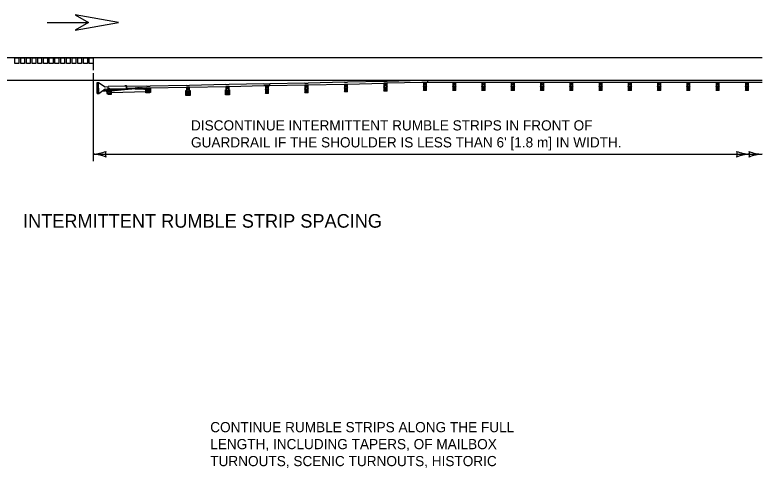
# Model space of a CAD drawing. Extents: x 49991.4 to 50021, y 49987.6 to 50011.4.
# Drawn here: x 50003.185 to 50007.589, y 49993.419 to 49996.09 of the extents above; entities that cross this region are included whole.
import ezdxf

# ---------------------------------------------------------------- set-up
doc = ezdxf.new("R2010")
doc.units = 0
for name, color, linetype in [('Level 1', 7, 'Continuous'), ('Level 2', 7, 'Continuous'), ('Level 3', 7, 'Continuous')]:
    doc.layers.add(name, color=color, linetype=linetype)

msp = doc.modelspace()

# ---------------------------------------------------------------- linework, layer by layer
at = {"layer": 'Level 1'}
for p, q in [((50003.3742, 49996.0445), (50003.6181, 49996.0445)), ((50003.3742, 49996.0443), (50003.6181, 49996.0443)), ((50007.5892, 49995.8373), (50001.3657, 49995.8373)), ((50003.628, 49995.7023), (50001.3657, 49995.7023)), ((50005.7236, 49995.7023), (50003.628, 49995.7023)), ((50003.6688, 49995.6911), (50003.6781, 49995.6913)), ((50003.6701, 49995.6259), (50003.6688, 49995.6911)), ((50003.6772, 49995.6261), (50003.6759, 49995.6913)), ((50003.6794, 49995.6261), (50003.6781, 49995.6913)), ((50003.6781, 49995.6913), (50003.7159, 49995.665)), ((50005.1274, 49995.693), (50004.9132, 49995.6884)), ((50005.1274, 49995.693), (50005.146, 49995.693)), ((50005.3603, 49995.6977), (50005.146, 49995.693)), ((50005.3603, 49995.6977), (50005.3789, 49995.6977)), ((50005.5841, 49995.7023), (50005.3789, 49995.6977)), ((50005.5841, 49995.6919), (50005.3789, 49995.6873)), ((50007.5892, 49995.7023), (50005.5841, 49995.7023)), ((50007.5892, 49995.6919), (50005.5841, 49995.6919)), ((50005.5932, 49995.6919), (50005.6118, 49995.6686)), ((50005.5932, 49995.6686), (50005.6118, 49995.6919)), ((50005.5932, 49995.6919), (50005.5932, 49995.6453)), ((50005.6118, 49995.6453), (50005.6118, 49995.6919)), ((50005.6196, 49995.6919), (50005.6196, 49995.7023)), ((50007.5892, 49995.7023), (50005.7236, 49995.7023)), ((50005.7657, 49995.6919), (50005.7843, 49995.6686)), ((50005.7657, 49995.6686), (50005.7843, 49995.6919)), ((50005.7657, 49995.6919), (50005.7657, 49995.6453)), ((50005.7843, 49995.6453), (50005.7843, 49995.6919)), ((50005.9382, 49995.6919), (50005.9568, 49995.6686)), ((50005.9382, 49995.6686), (50005.9568, 49995.6919)), ((50005.9382, 49995.6919), (50005.9382, 49995.6453)), ((50005.9568, 49995.6453), (50005.9568, 49995.6919)), ((50006.1107, 49995.6919), (50006.1293, 49995.6686)), ((50006.1107, 49995.6686), (50006.1293, 49995.6919)), ((50006.1107, 49995.6919), (50006.1107, 49995.6453)), ((50006.1293, 49995.6453), (50006.1293, 49995.6919)), ((50006.2832, 49995.6919), (50006.3018, 49995.6686)), ((50006.2832, 49995.6686), (50006.3018, 49995.6919)), ((50006.2832, 49995.6919), (50006.2832, 49995.6453)), ((50006.3018, 49995.6453), (50006.3018, 49995.6919)), ((50006.4557, 49995.6919), (50006.4743, 49995.6686)), ((50006.4557, 49995.6686), (50006.4743, 49995.6919)), ((50006.4557, 49995.6919), (50006.4557, 49995.6453)), ((50006.4743, 49995.6453), (50006.4743, 49995.6919)), ((50006.6282, 49995.6919), (50006.6468, 49995.6686)), ((50006.6282, 49995.6686), (50006.6468, 49995.6919)), ((50006.6282, 49995.6919), (50006.6282, 49995.6453)), ((50006.6468, 49995.6453), (50006.6468, 49995.6919)), ((50006.8007, 49995.6919), (50006.8193, 49995.6686)), ((50006.8007, 49995.6686), (50006.8193, 49995.6919)), ((50006.8007, 49995.6919), (50006.8007, 49995.6453)), ((50006.8193, 49995.6453), (50006.8193, 49995.6919)), ((50006.9732, 49995.6919), (50006.9918, 49995.6686)), ((50006.9732, 49995.6686), (50006.9918, 49995.6919)), ((50006.9732, 49995.6919), (50006.9732, 49995.6453)), ((50006.9918, 49995.6453), (50006.9918, 49995.6919)), ((50007.1457, 49995.6919), (50007.1643, 49995.6686)), ((50007.1457, 49995.6686), (50007.1643, 49995.6919)), ((50007.1457, 49995.6919), (50007.1457, 49995.6453)), ((50007.1643, 49995.6453), (50007.1643, 49995.6919)), ((50007.3182, 49995.6919), (50007.3368, 49995.6686)), ((50007.3182, 49995.6686), (50007.3368, 49995.6919)), ((50007.3182, 49995.6919), (50007.3182, 49995.6453)), ((50007.3368, 49995.6453), (50007.3368, 49995.6919)), ((50007.4907, 49995.6919), (50007.5093, 49995.6686)), ((50007.4907, 49995.6686), (50007.5093, 49995.6919)), ((50007.4907, 49995.6919), (50007.4907, 49995.6453)), ((50007.5093, 49995.6453), (50007.5093, 49995.6919)), ((50003.6794, 49995.6261), (50003.7161, 49995.654)), ((50003.7139, 49995.6524), (50003.7142, 49995.64)), ((50003.7159, 49995.665), (50003.7345, 49995.6673)), ((50003.7161, 49995.654), (50003.7348, 49995.6524)), ((50003.7271, 49995.6452), (50003.726, 49995.6452)), ((50003.726, 49995.6363), (50003.726, 49995.6452)), ((50003.7271, 49995.6531), (50003.7271, 49995.6261)), ((50003.7301, 49995.6524), (50003.7301, 49995.6261)), ((50003.7301, 49995.6291), (50003.7487, 49995.6524)), ((50003.7301, 49995.6524), (50003.7487, 49995.6291)), ((50003.7301, 49995.6524), (50003.7547, 49995.6524)), ((50003.8438, 49995.6695), (50003.7345, 49995.6673)), ((50003.7348, 49995.6524), (50003.7345, 49995.6673)), ((50003.8441, 49995.6546), (50003.7348, 49995.6524)), ((50003.7359, 49995.6577), (50003.7428, 49995.6579)), ((50003.736, 49995.6524), (50003.7359, 49995.6577)), ((50003.736, 49995.654), (50003.7429, 49995.6541)), ((50003.7429, 49995.6526), (50003.7428, 49995.6579)), ((50003.8931, 49995.6565), (50003.7487, 49995.6418)), ((50003.8932, 49995.6546), (50003.7487, 49995.6399)), ((50003.7487, 49995.6291), (50003.7487, 49995.6524)), ((50003.7517, 49995.6421), (50003.7517, 49995.6524)), ((50003.7547, 49995.6425), (50003.7547, 49995.6524)), ((50003.8493, 49995.6521), (50003.7547, 49995.6486)), ((50003.7783, 49995.643), (50003.7773, 49995.6448)), ((50003.7836, 49995.6435), (50003.7827, 49995.6453)), ((50003.789, 49995.644), (50003.788, 49995.6458)), ((50003.7944, 49995.6446), (50003.7934, 49995.6464)), ((50003.7998, 49995.6451), (50003.7988, 49995.6469)), ((50003.8051, 49995.6457), (50003.8042, 49995.6475)), ((50003.8105, 49995.6462), (50003.8095, 49995.648)), ((50003.8159, 49995.6468), (50003.8149, 49995.6486)), ((50003.8213, 49995.6473), (50003.8203, 49995.6491)), ((50003.8266, 49995.6479), (50003.8257, 49995.6497)), ((50003.832, 49995.6484), (50003.831, 49995.6502)), ((50003.8416, 49995.6717), (50003.8323, 49995.6715)), ((50003.8323, 49995.6693), (50003.8323, 49995.6715)), ((50003.8326, 49995.6522), (50003.8326, 49995.6544)), ((50003.842, 49995.6524), (50003.8326, 49995.6522)), ((50003.8374, 49995.649), (50003.8364, 49995.6508)), ((50003.842, 49995.6524), (50003.8416, 49995.6717)), ((50003.8427, 49995.6495), (50003.8418, 49995.6513)), ((50003.8441, 49995.6546), (50003.8438, 49995.6695)), ((50003.963, 49995.6697), (50003.8439, 49995.6673)), ((50003.963, 49995.6593), (50003.8441, 49995.6569)), ((50003.8481, 49995.6501), (50003.8471, 49995.6519)), ((50003.8535, 49995.6506), (50003.8525, 49995.6524)), ((50003.8588, 49995.6511), (50003.8579, 49995.6529)), ((50003.8642, 49995.6517), (50003.8633, 49995.6535)), ((50003.8696, 49995.6522), (50003.8686, 49995.654)), ((50003.875, 49995.6528), (50003.874, 49995.6546)), ((50003.8803, 49995.6533), (50003.8794, 49995.6551)), ((50003.8932, 49995.6537), (50003.8796, 49995.6533)), ((50003.8857, 49995.6539), (50003.8847, 49995.6557)), ((50003.891, 49995.6544), (50003.8901, 49995.6562)), ((50003.8931, 49995.6579), (50003.8932, 49995.6532)), ((50003.8932, 49995.6532), (50003.9444, 49995.6543)), ((50003.8949, 49995.6612), (50003.8962, 49995.6613)), ((50003.8949, 49995.6612), (50003.8949, 49995.658)), ((50003.8996, 49995.6581), (50003.8962, 49995.6613)), ((50003.9031, 49995.6614), (50003.9031, 49995.6581)), ((50003.9031, 49995.6614), (50003.9044, 49995.6614)), ((50003.9078, 49995.6582), (50003.9044, 49995.6614)), ((50003.9113, 49995.6616), (50003.9113, 49995.6583)), ((50003.9113, 49995.6616), (50003.9126, 49995.6616)), ((50003.916, 49995.6584), (50003.9126, 49995.6616)), ((50003.9195, 49995.6617), (50003.9208, 49995.6618)), ((50003.9195, 49995.6617), (50003.9195, 49995.6585)), ((50003.9242, 49995.6586), (50003.9208, 49995.6618)), ((50003.9276, 49995.6619), (50003.9277, 49995.6586)), ((50003.9276, 49995.6619), (50003.929, 49995.6619)), ((50003.9324, 49995.6587), (50003.929, 49995.6619)), ((50003.9359, 49995.6621), (50003.9359, 49995.6588)), ((50003.9359, 49995.6621), (50003.9372, 49995.6621)), ((50003.9406, 49995.6589), (50003.9372, 49995.6621)), ((50003.9444, 49995.6543), (50003.9443, 49995.659)), ((50003.9444, 49995.6543), (50003.9445, 49995.6522)), ((50003.9445, 49995.6522), (50003.9467, 49995.6523)), ((50003.9467, 49995.6523), (50003.9465, 49995.659)), ((50003.9467, 49995.6527), (50003.9478, 49995.6527)), ((50003.9477, 49995.659), (50003.9478, 49995.6527)), ((50003.9477, 49995.6585), (50003.9515, 49995.6585)), ((50003.9477, 49995.6567), (50003.9542, 49995.6569)), ((50003.9478, 49995.6549), (50003.9543, 49995.655)), ((50003.9516, 49995.6531), (50003.9478, 49995.6531)), ((50003.9515, 49995.6585), (50003.9516, 49995.6531)), ((50003.9543, 49995.655), (50003.9542, 49995.6569)), ((50003.9571, 49995.656), (50003.9543, 49995.6559)), ((50003.9571, 49995.6301), (50003.9571, 49995.6592)), ((50003.96, 49995.633), (50003.96, 49995.6593)), ((50003.963, 49995.6697), (50003.9817, 49995.6697)), ((50003.963, 49995.636), (50003.9817, 49995.6593)), ((50003.9817, 49995.636), (50003.963, 49995.6593)), ((50003.963, 49995.6593), (50003.963, 49995.636)), ((50003.963, 49995.6593), (50003.9817, 49995.6593)), ((50004.1959, 49995.6744), (50003.9817, 49995.6697)), ((50003.9817, 49995.6593), (50004.1959, 49995.664)), ((50003.9817, 49995.636), (50003.9817, 49995.6593)), ((50003.9846, 49995.6594), (50003.9846, 49995.633)), ((50004.1959, 49995.6744), (50004.2145, 49995.6744)), ((50004.1959, 49995.664), (50004.2145, 49995.6407)), ((50004.1959, 49995.6407), (50004.2145, 49995.664)), ((50004.1959, 49995.664), (50004.1959, 49995.6174)), ((50004.1959, 49995.664), (50004.2145, 49995.664)), ((50004.4288, 49995.6791), (50004.2145, 49995.6744)), ((50004.2145, 49995.664), (50004.4288, 49995.6686)), ((50004.2145, 49995.6174), (50004.2145, 49995.664)), ((50004.4258, 49995.6483), (50004.4288, 49995.6483)), ((50004.4258, 49995.6191), (50004.4258, 49995.6483)), ((50004.4288, 49995.6791), (50004.4474, 49995.6791)), ((50004.4288, 49995.6686), (50004.4474, 49995.6453)), ((50004.4288, 49995.6453), (50004.4474, 49995.6686)), ((50004.4288, 49995.6686), (50004.4288, 49995.622)), ((50004.4288, 49995.6686), (50004.4474, 49995.6686)), ((50004.4474, 49995.622), (50004.4288, 49995.6453)), ((50004.4288, 49995.622), (50004.4474, 49995.6453)), ((50004.4288, 49995.6453), (50004.4474, 49995.6453)), ((50004.6526, 49995.6837), (50004.4474, 49995.6791)), ((50004.4474, 49995.6686), (50004.6526, 49995.6733)), ((50004.4474, 49995.622), (50004.4474, 49995.6686)), ((50004.4474, 49995.6483), (50004.4504, 49995.6483)), ((50004.4504, 49995.6483), (50004.4504, 49995.6191)), ((50004.6526, 49995.6837), (50004.6881, 49995.6837)), ((50004.6526, 49995.6733), (50004.6881, 49995.6733)), ((50004.6617, 49995.6733), (50004.6803, 49995.65)), ((50004.6617, 49995.65), (50004.6803, 49995.6733)), ((50004.6617, 49995.6733), (50004.6617, 49995.6267)), ((50004.6803, 49995.6267), (50004.6617, 49995.65)), ((50004.6617, 49995.6267), (50004.6803, 49995.65)), ((50004.6617, 49995.65), (50004.6803, 49995.65)), ((50004.6803, 49995.6267), (50004.6803, 49995.6733)), ((50004.8945, 49995.6884), (50004.6881, 49995.6837)), ((50004.6881, 49995.6733), (50004.6881, 49995.6837)), ((50004.6881, 49995.6733), (50004.8945, 49995.6779)), ((50004.8945, 49995.6884), (50004.9132, 49995.6884)), ((50004.8945, 49995.6779), (50004.9132, 49995.6546)), ((50004.8945, 49995.6546), (50004.9132, 49995.6779)), ((50004.8945, 49995.6779), (50004.8945, 49995.6314)), ((50004.8945, 49995.6779), (50004.9132, 49995.6779)), ((50004.9132, 49995.6314), (50004.8945, 49995.6546)), ((50004.8945, 49995.6314), (50004.9132, 49995.6546)), ((50004.8945, 49995.6546), (50004.9132, 49995.6546)), ((50004.9132, 49995.6779), (50005.1274, 49995.6826)), ((50004.9132, 49995.6314), (50004.9132, 49995.6779)), ((50005.1274, 49995.6826), (50005.146, 49995.6593)), ((50005.1274, 49995.6593), (50005.146, 49995.6826)), ((50005.1274, 49995.6826), (50005.1274, 49995.636)), ((50005.1274, 49995.6826), (50005.146, 49995.6826)), ((50005.146, 49995.636), (50005.1274, 49995.6593)), ((50005.1274, 49995.636), (50005.146, 49995.6593)), ((50005.1274, 49995.6593), (50005.146, 49995.6593)), ((50005.146, 49995.6826), (50005.3603, 49995.6873)), ((50005.146, 49995.636), (50005.146, 49995.6826)), ((50005.3603, 49995.6873), (50005.3789, 49995.664)), ((50005.3603, 49995.664), (50005.3789, 49995.6873)), ((50005.3603, 49995.6873), (50005.3603, 49995.6407)), ((50005.3603, 49995.6873), (50005.3789, 49995.6873)), ((50005.3789, 49995.6407), (50005.3603, 49995.664)), ((50005.3603, 49995.6407), (50005.3789, 49995.664)), ((50005.3603, 49995.664), (50005.3789, 49995.664)), ((50005.3789, 49995.6407), (50005.3789, 49995.6873)), ((50005.6118, 49995.6453), (50005.5932, 49995.6686)), ((50005.5932, 49995.6453), (50005.6118, 49995.6686)), ((50005.5932, 49995.6686), (50005.6118, 49995.6686)), ((50005.6118, 49995.6453), (50005.5932, 49995.6453)), ((50005.7843, 49995.6453), (50005.7657, 49995.6686)), ((50005.7657, 49995.6453), (50005.7843, 49995.6686)), ((50005.7657, 49995.6686), (50005.7843, 49995.6686)), ((50005.7843, 49995.6453), (50005.7657, 49995.6453)), ((50005.9568, 49995.6453), (50005.9382, 49995.6686)), ((50005.9382, 49995.6453), (50005.9568, 49995.6686)), ((50005.9382, 49995.6686), (50005.9568, 49995.6686)), ((50005.9568, 49995.6453), (50005.9382, 49995.6453)), ((50006.1293, 49995.6453), (50006.1107, 49995.6686)), ((50006.1107, 49995.6453), (50006.1293, 49995.6686)), ((50006.1107, 49995.6686), (50006.1293, 49995.6686)), ((50006.1293, 49995.6453), (50006.1107, 49995.6453)), ((50006.3018, 49995.6453), (50006.2832, 49995.6686)), ((50006.2832, 49995.6453), (50006.3018, 49995.6686)), ((50006.2832, 49995.6686), (50006.3018, 49995.6686)), ((50006.3018, 49995.6453), (50006.2832, 49995.6453)), ((50006.4743, 49995.6453), (50006.4557, 49995.6686)), ((50006.4557, 49995.6453), (50006.4743, 49995.6686)), ((50006.4557, 49995.6686), (50006.4743, 49995.6686)), ((50006.4743, 49995.6453), (50006.4557, 49995.6453)), ((50006.6468, 49995.6453), (50006.6282, 49995.6686)), ((50006.6282, 49995.6453), (50006.6468, 49995.6686)), ((50006.6282, 49995.6686), (50006.6468, 49995.6686)), ((50006.6468, 49995.6453), (50006.6282, 49995.6453)), ((50006.8193, 49995.6453), (50006.8007, 49995.6686)), ((50006.8007, 49995.6453), (50006.8193, 49995.6686)), ((50006.8007, 49995.6686), (50006.8193, 49995.6686)), ((50006.8193, 49995.6453), (50006.8007, 49995.6453)), ((50006.9918, 49995.6453), (50006.9732, 49995.6686)), ((50006.9732, 49995.6453), (50006.9918, 49995.6686)), ((50006.9732, 49995.6686), (50006.9918, 49995.6686)), ((50006.9918, 49995.6453), (50006.9732, 49995.6453)), ((50007.1643, 49995.6453), (50007.1457, 49995.6686)), ((50007.1457, 49995.6453), (50007.1643, 49995.6686)), ((50007.1457, 49995.6686), (50007.1643, 49995.6686)), ((50007.1643, 49995.6453), (50007.1457, 49995.6453)), ((50007.3368, 49995.6453), (50007.3182, 49995.6686)), ((50007.3182, 49995.6453), (50007.3368, 49995.6686)), ((50007.3182, 49995.6686), (50007.3368, 49995.6686)), ((50007.3368, 49995.6453), (50007.3182, 49995.6453)), ((50007.5093, 49995.6453), (50007.4907, 49995.6686)), ((50007.4907, 49995.6453), (50007.5093, 49995.6686)), ((50007.4907, 49995.6686), (50007.5093, 49995.6686)), ((50007.5093, 49995.6453), (50007.4907, 49995.6453)), ((50003.6701, 49995.6259), (50003.6794, 49995.6261)), ((50003.7142, 49995.64), (50003.6972, 49995.6396)), ((50003.726, 49995.6418), (50003.7195, 49995.6418)), ((50003.7195, 49995.6418), (50003.7195, 49995.6399)), ((50003.726, 49995.6399), (50003.7195, 49995.6399)), ((50003.7222, 49995.6382), (50003.7222, 49995.6436)), ((50003.7222, 49995.6436), (50003.726, 49995.6436)), ((50003.726, 49995.6382), (50003.7222, 49995.6382)), ((50003.7271, 49995.6363), (50003.726, 49995.6363)), ((50003.7271, 49995.6261), (50003.7517, 49995.6261)), ((50003.7301, 49995.6291), (50003.7487, 49995.6291)), ((50003.7328, 49995.6232), (50003.7328, 49995.6261)), ((50003.7328, 49995.6232), (50003.7547, 49995.6232)), ((50003.7514, 49995.6402), (50003.7505, 49995.642)), ((50003.7517, 49995.6261), (50003.7517, 49995.6402)), ((50003.7547, 49995.6232), (50003.7547, 49995.6406)), ((50003.9571, 49995.637), (50003.7547, 49995.6296)), ((50003.7568, 49995.6408), (50003.7558, 49995.6426)), ((50003.7622, 49995.6413), (50003.7612, 49995.6431)), ((50003.7676, 49995.6419), (50003.7666, 49995.6437)), ((50003.7729, 49995.6424), (50003.7719, 49995.6442)), ((50003.9793, 49995.6301), (50003.9571, 49995.6301)), ((50003.9846, 49995.633), (50003.96, 49995.633)), ((50003.9817, 49995.636), (50003.963, 49995.636)), ((50003.9793, 49995.6301), (50003.9793, 49995.633)), ((50004.1929, 49995.6437), (50004.1959, 49995.6437)), ((50004.1929, 49995.6144), (50004.1929, 49995.6437)), ((50004.2175, 49995.6144), (50004.1929, 49995.6144)), ((50004.2145, 49995.6174), (50004.1959, 49995.6407)), ((50004.1959, 49995.6174), (50004.2145, 49995.6407)), ((50004.1959, 49995.6407), (50004.2145, 49995.6407)), ((50004.2145, 49995.6174), (50004.1959, 49995.6174)), ((50004.2145, 49995.6437), (50004.2175, 49995.6437)), ((50004.2175, 49995.6437), (50004.2175, 49995.6144)), ((50004.4504, 49995.6191), (50004.4258, 49995.6191)), ((50004.4474, 49995.622), (50004.4288, 49995.622)), ((50004.6803, 49995.6267), (50004.6617, 49995.6267)), ((50004.9132, 49995.6314), (50004.8945, 49995.6314)), ((50005.146, 49995.636), (50005.1274, 49995.636)), ((50005.3789, 49995.6407), (50005.3603, 49995.6407))]:
    msp.add_line(p, q, dxfattribs=at)
for points in [[(50003.5401, 49995.9993), (50003.7954, 49996.0443), (50003.5401, 49996.0896), (50003.6178, 49996.0443)], [(50003.1849, 49995.8373), (50003.2074, 49995.8373), (50003.2074, 49995.8036), (50003.1849, 49995.8036)], [(50003.2186, 49995.8373), (50003.2411, 49995.8373), (50003.2411, 49995.8036), (50003.2186, 49995.8036)], [(50003.2523, 49995.8373), (50003.2748, 49995.8373), (50003.2748, 49995.8036), (50003.2523, 49995.8036)], [(50003.286, 49995.8373), (50003.3085, 49995.8373), (50003.3085, 49995.8036), (50003.286, 49995.8036)], [(50003.3197, 49995.8373), (50003.3422, 49995.8373), (50003.3422, 49995.8036), (50003.3197, 49995.8036)], [(50003.3534, 49995.8373), (50003.3759, 49995.8373), (50003.3759, 49995.8036), (50003.3534, 49995.8036)], [(50003.3871, 49995.8373), (50003.4096, 49995.8373), (50003.4096, 49995.8036), (50003.3871, 49995.8036)], [(50003.4208, 49995.8373), (50003.4433, 49995.8373), (50003.4433, 49995.8036), (50003.4208, 49995.8036)], [(50003.4545, 49995.8373), (50003.477, 49995.8373), (50003.477, 49995.8036), (50003.4545, 49995.8036)], [(50003.4882, 49995.8373), (50003.5107, 49995.8373), (50003.5107, 49995.8036), (50003.4882, 49995.8036)], [(50003.5219, 49995.8373), (50003.5444, 49995.8373), (50003.5444, 49995.8036), (50003.5219, 49995.8036)], [(50003.5556, 49995.8373), (50003.5781, 49995.8373), (50003.5781, 49995.8036), (50003.5556, 49995.8036)], [(50003.5893, 49995.8373), (50003.6118, 49995.8373), (50003.6118, 49995.8036), (50003.5893, 49995.8036)], [(50003.623, 49995.8373), (50003.6455, 49995.8373), (50003.6455, 49995.8036), (50003.623, 49995.8036)]]:
    msp.add_lwpolyline(points, close=True, dxfattribs=at)
at = {"layer": 'Level 2'}
msp.add_line((50003.6455, 49995.8036), (50003.6455, 49995.7636), dxfattribs=at)
at = {"layer": 'Level 3'}
for p, q in [((50003.6455, 49995.7465), (50003.6455, 49995.2288)), ((50003.6455, 49995.2688), (50007.5556, 49995.2688))]:
    msp.add_line(p, q, dxfattribs=at)
for centre, radius, start, end in [((50003.634, 49995.5016), 0.233, 272.8273, 292.0772), ((50003.6364, 49995.0467), 0.2223, 67.456, 87.6395), ((50003.7737, 49995.2688), 0.0548, 162.1388, 197.8612), ((50007.5247, 49995.491), 0.2223, 247.456, 267.6395), ((50007.3874, 49995.2688), 0.0548, 342.1388, 17.8612), ((50007.5271, 49995.0361), 0.233, 92.8273, 112.0772), ((50007.5982, 49995.4907), 0.2223, 247.456, 267.6395), ((50007.4608, 49995.2686), 0.0548, 342.1388, 17.8612), ((50007.6005, 49995.0358), 0.233, 92.8273, 112.0772)]:
    msp.add_arc(centre, radius, start, end, dxfattribs=at)

# ---------------------------------------------------------------- texts
at = {"layer": 'Level 2'}
for s, height, p in [('DISCONTINUE INTERMITTENT RUMBLE STRIPS IN FRONT OF ', 0.06, (50004.2227, 49995.4088)), ("GUARDRAIL IF THE SHOULDER IS LESS THAN 6' [1.8 m] IN WIDTH.", 0.06, (50004.2227, 49995.3088)), ('INTERMITTENT RUMBLE STRIP SPACING', 0.08, (50003.2326, 49994.8357)), ('CONTINUE RUMBLE STRIPS ALONG THE FULL', 0.06, (50004.336, 49993.6302)), ('LENGTH, INCLUDING TAPERS, OF MAILBOX', 0.06, (50004.336, 49993.5302)), ('TURNOUTS, SCENIC TURNOUTS, HISTORIC', 0.06, (50004.336, 49993.4302))]:
    msp.add_text(s, height=height, dxfattribs=at).set_placement(p)

doc.saveas('drawing.dxf')
